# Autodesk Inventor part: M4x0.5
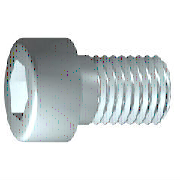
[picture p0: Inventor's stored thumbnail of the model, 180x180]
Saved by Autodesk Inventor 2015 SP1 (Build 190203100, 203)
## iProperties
IsCustomPart: 1
Company: 한국ATC센터
Created: 2009-02
Part Number: M4x0.5
Material: 강, 연강
Description: 6각머리 태핑 나사
Document SubType Name: Modeling
Standard: KS B 1003
Designer: KYOUNG IL JANG
Standards Organization: KS
Language: ko-KR
Size Designation: M 4 x 12
Categories: <MemberInstance><Categories><Category DisplayName="조임쇠" InternalName="e4da775c-781d-43d5-af7c-5136215cf5a6" Mnemonic="FSTN"><Category DisplayName="볼트" InternalN
Density: 1 g/cm^3
Appearance: 금속-강
Author: KYOUNG IL JANG
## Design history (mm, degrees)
sketch "스케치1"
  geometry: L1 (-1, 0)-(12, 0); L2 (12, 0)-(12, 2); L3 (12, 2)-(1.75, 2); L4 (1.75, 2)-(1.32, 2); L5 (1.32, 2)-(0, 2); L6 (0, 2)-(0, 3.5); L7 (0, 3.5)-(-4, 3.5); L8 (-4, 3.5)-(-4, 1.732); L9 (-4, 1.732)-(-2, 1.732); L10 (-2, 1.732)-(-1, 0); L11 (-7.2, 0)-(15.2, 0) reference; L12 (0, -0.7)-(0, 4.2) reference; L13 (1.75, 2)-(0, 2)
  constraints: 22 end point, 6 parallel, 2 collinear, 2 perpendicular, 1 horizontal, 1 point on line
  dimensions: "d1" = 10.25 distance from line of L3.end L2 (= GEL); "d2" = 0.42952 distance of L4.end L3.end (computed from GAL); "d3" = 4 distance between parallel lines of L8 L6 (= KOH); "d4" = 2 distance of L8.end L9.end (= INTI); "d5" = 60 deg angle of L10 L1; "d6" = 4 diameter of L3 L1 (= GD); "d7" = 4 diameter of L5 L1 (= BDM); "d8" = 3.4641 diameter of L9 L1 (= 1.1547 x SW); "d9" = 7 diameter of L7 L1 (= KOD); "d26" = 12 distance between parallel lines of L12 L2 (= NLG)
revolve "본체" sketch "스케치1" stored, may be unused: angle "d10" = 90 deg
sketch "스케치2"
  geometry: L1 (0, -4.9)-(0, 4.9) reference; L2 (-4.9, 0)-(4.9, 0) reference; L3 (1.732, 0)-(0.866, -1.5); L4 (0.866, -1.5)-(-0.866, -1.5); L5 (-0.866, -1.5)-(-1.732, 0); L6 (-1.732, 0)-(-0.866, 1.5); L7 (-0.866, 1.5)-(0.866, 1.5); L8 (0.866, 1.5)-(1.732, 0); 2 further points
  constraints: 12 end point, 1 coincident, 1 horizontal alignment, 1 point on line, 12 other
extrude "슬롯" join sketch "스케치2" stored distance "d11" = 10; taper "d12" = 0 deg
workplane "Work Plane1"
fillet "Fillet2" dims "d30" = 0.1 (= R)
body "Solid1"
fillet "모깎기1" dims "d17" = 0.4 (= RR)
feature "스레드" dims "d13" = 10.25 (= GEL), "d14" = 0
chamfer "모따기1" distance "d15" = 0.42941 (= -0.5 x SPD + 0.5 x GD); stored, may be unused: second distance "d16" = 0.42941 (= GUL), angle "d27" = 45 deg
other parameters: "GD" = 4 (= NND) [user parameter; used in 2 equation terms], "NLG" = 12 [user parameter; used in 1 equation term], "GEL" = 10.25 [user parameter; used in 2 equation terms], "KOD" = 7 [user parameter; used in 1 equation term], "KOH" = 4 [user parameter; used in 1 equation term], "INTI" = 2 [user parameter; used in 1 equation term], "GAL" = 0.42941 (= 0.61345 x PTC) [user parameter; used in 1 equation term], "GUL" = 0.42941 (= 0.61345 x PTC) [user parameter; used in 1 equation term], "BDM" = 4 (= NND) [user parameter; used in 1 equation term], "SW" = 3 [user parameter; used in 2 equation terms], "RR" = 0.4 [user parameter; used in 1 equation term], "SPD" = 3.14117 (= NND - 1.2269 x PTC) [user parameter; used in 1 equation term], "d19" = 0, "d28" = 0, "d29" = 0, "R" = 0.1 [user parameter; used in 1 equation term], "PHH" = 0.2 [user parameter], "GD1" = 3.14117 (= THREADDIA - 1.2269 x PTC) [user parameter], "THREADDIA" = 4 [user parameter; used in 1 equation term], "FAWI" = 45 deg [user parameter], "TPU" = 14.28571 (computed from PTC) [user parameter], "PTC" = 0.7 [user parameter; used in 5 equation terms], "NND" = 4 [user parameter; used in 3 equation terms], "TOA" = 30 deg [user parameter], "E0" = 3.465 (= 1.155 x SW) [user parameter]
